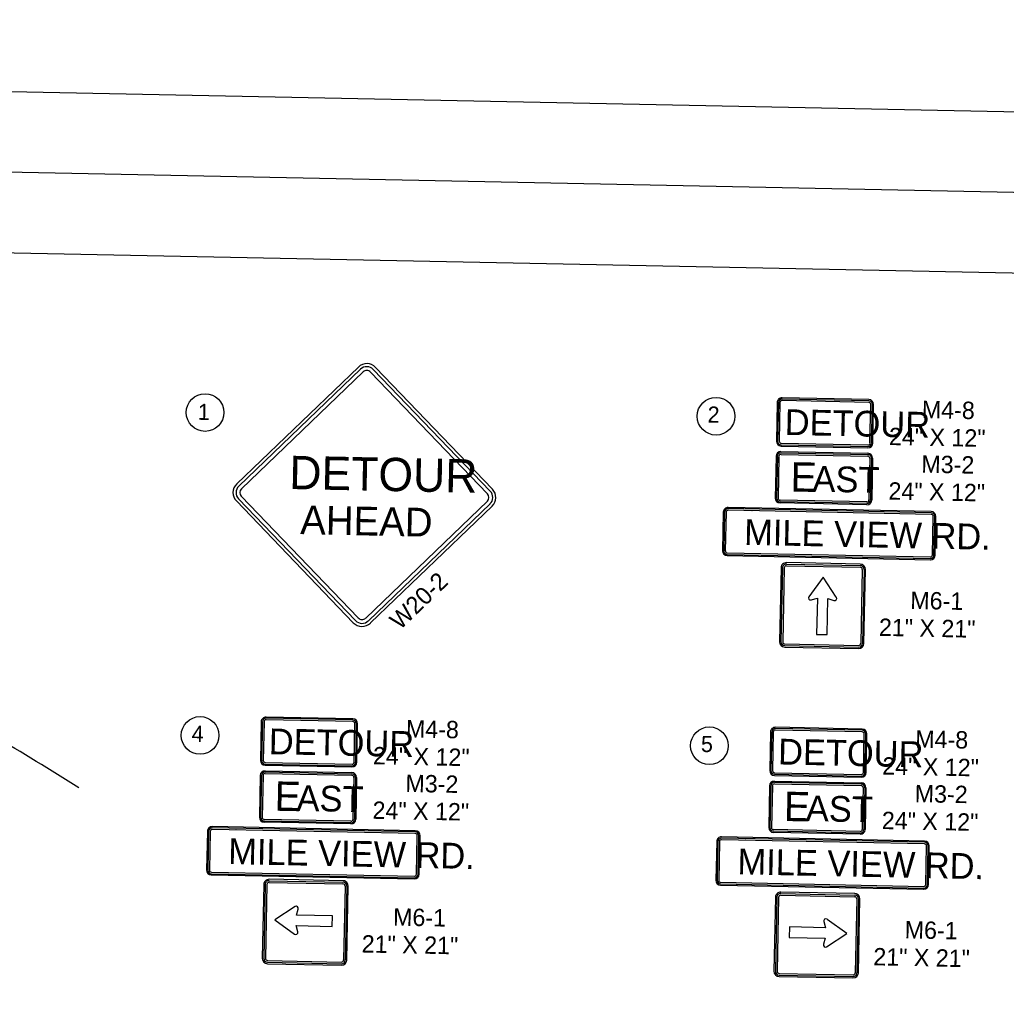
# Model space of a CAD drawing. Extents: x 299354 to 1325680, y 96128 to 228242.
# Drawn here: x 1319839 to 1322906, y 151826 to 154903 of the extents above; entities that cross this region are included whole.
import ezdxf

# ---------------------------------------------------------------- set-up
doc = ezdxf.new("R2010")
doc.units = 0
for name, color, linetype in [('CA-TEXT', 7, 'Continuous'), ('Level 4', 7, 'Continuous'), ('P_SGN_Cell', 7, 'Continuous'), ('PLT_Sheet_Border', 7, 'Continuous'), ('PLT_Sheet_Info', 7, 'Continuous')]:
    doc.layers.add(name, color=color, linetype=linetype)

msp = doc.modelspace()

# ---------------------------------------------------------------- linework, layer by layer
at = {"layer": 'CA-TEXT'}
for centre in [(1320414.9, 153681.8), (1322003.9, 153670.3), (1320399.5, 152677.4), (1321983.2, 152645.5)]:
    msp.add_circle(centre, 58.6, dxfattribs=at)
at = {"layer": 'Level 4'}
msp.add_spline([(1320022.4, 152514.1), (1319477, 152813.3), (1318978.2, 152936.2), (1318427, 152947.3), (1317374.5, 152955.9)], degree=3, dxfattribs=at)
at = {"layer": 'P_SGN_Cell'}
for p, q in [((1322205.9, 153560.4), (1322476.1, 153555)), ((1322206.1, 153556.6), (1322476, 153551.2)), ((1322190.8, 153545.7), (1322188.2, 153415.7)), ((1322194.6, 153545.6), (1322192, 153415.6)), ((1322199.6, 153545.5), (1322197, 153415.5)), ((1322206, 153551.6), (1322475.9, 153546.2)), ((1322482, 153539.8), (1322479.4, 153409.9)), ((1322487, 153539.7), (1322484.4, 153409.8)), ((1322490.8, 153539.7), (1322488.2, 153409.7)), ((1322472.9, 153395), (1322202.9, 153400.4)), ((1322472.9, 153398.7), (1322203, 153404.2)), ((1322473, 153403.7), (1322203.1, 153409.2)), ((1322206, 153198.7), (1322201.4, 152969.1)), ((1322210.4, 153198.6), (1322205.8, 152969)), ((1322215.9, 153198.5), (1322211.2, 152968.9)), ((1322222.6, 153205), (1322452.2, 153200.3)), ((1322222.7, 153210.4), (1322452.3, 153205.8)), ((1322452.4, 153210.2), (1322222.8, 153214.8)), ((1322458.6, 153193.7), (1322454, 152964)), ((1322464.1, 153193.5), (1322459.5, 152963.9)), ((1322463.8, 152963.8), (1322468.5, 153193.5)), ((1322336.7, 153169.8), (1322292.9, 153108.8)), ((1322378, 153107.1), (1322336.7, 153169.8)), ((1322300, 153098.7), (1322319, 153104)), ((1322319, 153104), (1322316.7, 152991.9)), ((1322349.5, 152991.3), (1322351.8, 153103.3)), ((1322351.8, 153103.3), (1322370.5, 153097.2)), ((1322316.7, 152991.9), (1322349.5, 152991.3)), ((1322217.5, 152952.4), (1322447.1, 152947.7)), ((1322217.6, 152956.7), (1322447.2, 152952.1)), ((1322217.7, 152962.2), (1322447.3, 152957.6)), ((1320586.5, 152552.8), (1320583.8, 152422.9)), ((1320590.2, 152552.8), (1320587.6, 152422.8)), ((1320595.2, 152552.7), (1320592.6, 152422.7)), ((1320601.6, 152567.5), (1320871.7, 152562.1)), ((1320601.6, 152558.8), (1320871.5, 152553.4)), ((1320601.7, 152563.8), (1320871.6, 152558.4)), ((1320877.6, 152547), (1320875, 152417)), ((1320882.6, 152546.9), (1320880, 152416.9)), ((1320886.4, 152546.8), (1320883.8, 152416.8)), ((1322170.2, 152520.9), (1322167.6, 152391)), ((1322174, 152520.9), (1322171.3, 152390.9)), ((1322179, 152520.8), (1322176.3, 152390.8)), ((1322185.3, 152535.6), (1322455.5, 152530.2)), ((1322185.3, 152526.9), (1322455.3, 152521.5)), ((1322185.4, 152531.9), (1322455.4, 152526.5)), ((1322461.4, 152515.1), (1322458.8, 152385.1)), ((1322466.4, 152515), (1322463.8, 152385)), ((1322470.1, 152514.9), (1322467.5, 152384.9)), ((1320868.7, 152410.9), (1320598.7, 152416.3)), ((1320868.5, 152402.1), (1320598.5, 152407.6)), ((1320868.6, 152405.9), (1320598.6, 152411.3)), ((1322452.4, 152379), (1322182.5, 152384.4)), ((1322452.2, 152370.2), (1322182.3, 152375.7)), ((1322452.3, 152374), (1322182.4, 152379.4)), ((1320597.6, 152213.9), (1320593, 151984.3)), ((1320602, 152213.8), (1320597.4, 151984.2)), ((1320607.5, 152213.7), (1320602.8, 151984.1)), ((1320614.2, 152220.2), (1320843.8, 152215.5)), ((1320614.3, 152225.6), (1320843.9, 152221)), ((1320844, 152225.4), (1320614.4, 152230)), ((1320850.2, 152208.8), (1320845.6, 151979.2)), ((1320855.7, 152208.7), (1320851.1, 151979.1)), ((1320855.4, 151979), (1320860.1, 152208.6)), ((1322188.7, 152174.1), (1322184, 151944.4)), ((1322193, 152174), (1322188.4, 151944.4)), ((1322198.5, 152173.9), (1322193.9, 151944.2)), ((1322205.2, 152180.3), (1322434.8, 152175.7)), ((1322205.3, 152185.8), (1322434.9, 152181.2)), ((1322435, 152185.5), (1322205.4, 152190.2)), ((1322441.3, 152169), (1322436.6, 151939.4)), ((1320695, 152145.1), (1320632.3, 152103.7)), ((1322446.7, 152168.9), (1322442.1, 151939.2)), ((1322446.5, 151939.2), (1322451.1, 152168.8)), ((1320698.8, 152118.8), (1320704.9, 152137.6)), ((1320810.9, 152116.5), (1320698.8, 152118.8)), ((1320810.2, 152083.7), (1320810.9, 152116.5)), ((1320632.3, 152103.7), (1320693.3, 152059.9)), ((1320703.5, 152067), (1320698.1, 152086)), ((1320698.1, 152086), (1320810.2, 152083.7)), ((1322232.4, 152081.7), (1322231.7, 152048.9)), ((1322344.4, 152079.5), (1322232.4, 152081.7)), ((1322339.1, 152098.4), (1322344.4, 152079.5)), ((1322410.3, 152061.7), (1322349.3, 152105.5)), ((1322231.7, 152048.9), (1322343.8, 152046.6)), ((1322343.8, 152046.6), (1322337.7, 152027.9)), ((1322347.5, 152020.4), (1322410.3, 152061.7)), ((1320609.1, 151967.6), (1320838.7, 151962.9)), ((1320609.2, 151971.9), (1320838.8, 151967.3)), ((1320609.3, 151977.4), (1320838.9, 151972.8)), ((1322200.1, 151927.7), (1322429.8, 151923.1)), ((1322200.2, 151932.1), (1322429.8, 151927.5)), ((1322200.3, 151937.5), (1322430, 151932.9))]:
    msp.add_line(p, q, dxfattribs=at)
for points in [[(1320891.9, 153823.3), (1320513.3, 153459.6)], [(1320898.5, 153816.4), (1320519.9, 153452.7)], [(1320906.8, 153807.8), (1320528.2, 153444.2)], [(1321293.2, 153428.8), (1320929.5, 153807.4)], [(1321301.8, 153437), (1320938.1, 153815.6)], [(1321308.7, 153443.6), (1320945, 153822.2)], [(1322194, 153712.8), (1322191.6, 153592.9)], [(1322197.7, 153712.8), (1322195.3, 153592.8)], [(1322202.7, 153712.7), (1322200.3, 153592.7)], [(1322479, 153713.3), (1322209.1, 153718.8)], [(1322479.1, 153718.3), (1322209.2, 153723.8)], [(1322479.2, 153722.1), (1322209.3, 153727.5)], [(1322482.7, 153587), (1322485.2, 153707)], [(1322487.7, 153586.9), (1322490.2, 153706.9)], [(1322491.5, 153586.8), (1322493.9, 153706.8)], [(1322206.4, 153586.3), (1322476.4, 153580.9)], [(1322206.2, 153577.6), (1322476.2, 153572.1)], [(1322206.3, 153581.3), (1322476.3, 153575.9)], [(1320512.3, 153406.6), (1320875.9, 153028)], [(1320519.1, 153413.2), (1320882.8, 153034.6)], [(1320527.7, 153421.4), (1320891.4, 153042.8)], [(1320914.4, 153042.6), (1321292.9, 153406.2)], [(1320922.7, 153034.1), (1321301.2, 153397.6)], [(1320929.3, 153027.2), (1321307.8, 153390.7)], [(1322026.5, 153371.8), (1322024.1, 153251.9)], [(1322030.3, 153371.8), (1322027.8, 153251.8)], [(1322035.3, 153371.7), (1322032.8, 153251.7)], [(1322673, 153365.1), (1322041.6, 153377.8)], [(1322673.1, 153370.1), (1322041.7, 153382.8)], [(1322673.2, 153373.8), (1322041.8, 153386.8)], [(1322676.7, 153238.7), (1322679.1, 153358.7)], [(1322681.7, 153238.6), (1322684.1, 153358.6)], [(1322685.5, 153238.6), (1322687.9, 153358.5)], [(1322038.8, 153236.6), (1322670.9, 153223.8)], [(1322038.9, 153240.3), (1322670.2, 153227.6)], [(1322039, 153245.3), (1322670.3, 153232.6)], [(1320874.6, 152720.5), (1320604.7, 152725.9)], [(1320874.7, 152725.5), (1320604.8, 152730.9)], [(1320874.8, 152729.2), (1320604.9, 152734.7)], [(1320589.6, 152720), (1320587.2, 152600)], [(1320593.3, 152719.9), (1320590.9, 152599.9)], [(1320598.3, 152719.8), (1320595.9, 152599.8)], [(1320878.4, 152594.1), (1320880.8, 152714.1)], [(1320883.4, 152594), (1320885.8, 152714)], [(1320887.1, 152594), (1320889.5, 152713.9)], [(1322458.4, 152688.6), (1322188.5, 152694)], [(1322458.6, 152697.3), (1322188.6, 152702.8)], [(1322458.5, 152693.6), (1322188.6, 152699)], [(1322173.3, 152688.1), (1322170.9, 152568.1)], [(1322177.1, 152688), (1322174.7, 152568)], [(1322182.1, 152687.9), (1322179.7, 152567.9)], [(1322462.1, 152562.2), (1322464.5, 152682.2)], [(1322467.1, 152562.1), (1322469.5, 152682.1)], [(1322470.9, 152562.1), (1322473.3, 152682)], [(1320601.9, 152588.5), (1320871.9, 152583)], [(1320601.9, 152584.7), (1320871.8, 152579.3)], [(1320602, 152593.5), (1320872, 152588)], [(1322185.6, 152552.8), (1322455.6, 152547.4)], [(1322185.7, 152556.6), (1322455.6, 152551.1)], [(1322185.8, 152561.6), (1322455.7, 152556.1)], [(1321068.6, 152372.2), (1320437.2, 152384.9)], [(1321068.7, 152377.2), (1320437.3, 152389.9)], [(1321068.8, 152381), (1320437.4, 152393.9)], [(1320422.1, 152379), (1320419.7, 152259)], [(1320425.9, 152378.9), (1320423.5, 152258.9)], [(1320430.9, 152378.8), (1320428.5, 152258.8)], [(1321072.3, 152245.9), (1321074.7, 152365.9)], [(1321077.3, 152245.8), (1321079.7, 152365.8)], [(1321081.1, 152245.7), (1321083.5, 152365.7)], [(1322652.5, 152345.3), (1322021.1, 152358)], [(1322652.5, 152349.1), (1322021.2, 152362)], [(1322005.9, 152347.1), (1322003.5, 152227.1)], [(1322009.6, 152347), (1322007.2, 152227.1)], [(1322014.6, 152346.9), (1322012.2, 152227)], [(1322652.4, 152340.3), (1322021, 152353)], [(1322656.1, 152214), (1322658.5, 152334)], [(1322661.1, 152213.9), (1322663.5, 152333.9)], [(1322664.8, 152213.8), (1322667.2, 152333.8)], [(1320434.4, 152243.7), (1321066.5, 152231)], [(1320434.5, 152247.5), (1321065.8, 152234.8)], [(1320434.6, 152252.5), (1321065.9, 152239.8)], [(1322018.2, 152215.6), (1322649.6, 152202.9)], [(1322018.2, 152211.8), (1322650.3, 152199.1)], [(1322018.3, 152220.6), (1322649.7, 152207.9)]]:
    msp.add_lwpolyline(points, dxfattribs=at)
for centre, radius, start, end in [((1320917.9, 153796.3), 37.5, 43.8449, 133.8468), ((1320917.9, 153796.3), 28, 43.8449, 133.8468), ((1320917.9, 153796.3), 16.1, 43.8449, 133.8468), ((1322209, 153712.5), 15, 88.8468, 178.8468), ((1322209, 153712.5), 11.2, 88.8468, 178.8468), ((1322209, 153712.5), 6.25, 88.8468, 178.8468), ((1322209, 153712.5), 6.25, 88.8468, 96.1883), ((1322478.9, 153707.1), 6.25, 358.8468, 88.8468), ((1322478.9, 153707.1), 11.2, 358.8468, 88.8468), ((1322478.9, 153707.1), 15, 358.8468, 88.8468), ((1322206.6, 153592.6), 15, 178.8468, 268.8468), ((1322206.6, 153592.6), 11.2, 178.8468, 268.8468), ((1322206.6, 153592.6), 6.25, 178.8468, 268.8468), ((1322476.5, 153587.1), 15, 268.8468, 358.8468), ((1322476.5, 153587.1), 11.2, 268.8468, 358.8468), ((1322476.5, 153587.1), 6.25, 268.8468, 358.8468), ((1322205.8, 153545.4), 15, 89.6119, 178.8462), ((1322205.8, 153545.4), 11.2, 88.8462, 178.8462), ((1322475.8, 153540), 15, 358.8462, 88.8462), ((1322205.8, 153545.4), 6.25, 88.8462, 178.8462), ((1322475.8, 153540), 6.25, 358.8462, 88.8462), ((1322475.8, 153540), 11.2, 358.8462, 88.8462), ((1320539.3, 153432.6), 37.5, 133.8468, 223.8468), ((1320539.3, 153432.6), 28, 133.8468, 223.8468), ((1320539.3, 153432.6), 16.1, 133.8468, 223.8468), ((1321281.6, 153417.6), 28, 313.8468, 43.8468), ((1321281.6, 153417.6), 37.5, 313.8468, 43.8468), ((1321281.6, 153417.6), 16.1, 313.8468, 43.8468), ((1322203.2, 153415.4), 15, 178.8462, 268.8462), ((1322203.2, 153415.4), 11.2, 178.8462, 268.8462), ((1322203.2, 153415.4), 6.25, 178.8462, 268.8462), ((1322473.2, 153410), 11.2, 268.8462, 358.8462), ((1322473.2, 153410), 15, 268.8462, 358.8462), ((1322473.2, 153410), 6.25, 268.8462, 358.8462), ((1322041.5, 153371.7), 15, 88.8468, 178.8468), ((1322041.5, 153371.5), 11.2, 88.8468, 178.8468), ((1322041.5, 153371.5), 6.25, 88.8468, 178.8468), ((1322115.9, 153370), 6.25, 88.8468, 96.1883), ((1322672.9, 153358.8), 11.2, 358.8468, 88.8468), ((1322672.9, 153358.8), 15, 358.8468, 88.8468), ((1322672.9, 153358.8), 6.25, 358.8468, 88.8468), ((1322039.1, 153251.6), 15, 178.8468, 268.8468), ((1322039.1, 153251.6), 11.2, 178.8468, 268.8468), ((1322039.1, 153251.6), 6.25, 178.8468, 268.8468), ((1322670.5, 153238.9), 15, 268.8468, 358.8468), ((1322670.5, 153238.9), 11.2, 268.8468, 358.8468), ((1322670.5, 153238.9), 6.25, 268.8468, 358.8468), ((1322222.4, 153198.4), 16.4, 88.8468, 178.8468), ((1322222.4, 153198.4), 12, 88.8468, 178.8468), ((1322222.4, 153198.4), 6.56, 88.8468, 178.8468), ((1322452.1, 153193.8), 6.56, 358.8468, 88.8468), ((1322452.1, 153193.8), 12, 358.8468, 88.8468), ((1322452.1, 153193.8), 16.4, 59.4503, 88.8468), ((1322452.1, 153193.8), 16.4, 358.8468, 88.8468), ((1322298.2, 153105), 6.56, 144.3172, 285.6494), ((1322372.6, 153103.5), 6.56, 252.0442, 33.3765), ((1320903, 153053.9), 28, 223.854, 314.4977), ((1320903, 153053.9), 16.1, 223.854, 314.4977), ((1320903, 153053.9), 37.5, 223.854, 314.4977), ((1322217.8, 152968.8), 16.4, 178.8468, 268.8468), ((1322217.8, 152968.8), 12, 178.8468, 268.8468), ((1322217.8, 152968.8), 6.56, 178.8468, 268.8468), ((1322447.4, 152964.1), 16.4, 268.8468, 358.8468), ((1322447.4, 152964.1), 12, 268.8468, 358.8468), ((1322447.4, 152964.1), 6.56, 268.8468, 358.8468), ((1320604.6, 152719.7), 15, 88.8468, 178.8468), ((1320604.6, 152719.7), 11.2, 88.8468, 178.8468), ((1320604.6, 152719.7), 6.25, 88.8468, 178.8468), ((1320604.6, 152719.7), 6.25, 88.8468, 96.1883), ((1320874.5, 152714.2), 11.2, 358.8468, 88.8468), ((1320874.5, 152714.2), 15, 358.8468, 88.8468), ((1320874.5, 152714.2), 6.25, 358.8468, 88.8468), ((1322188.3, 152687.8), 15, 88.8468, 178.8468), ((1322188.3, 152687.8), 11.2, 88.8468, 178.8468), ((1322188.3, 152687.8), 6.25, 88.8468, 178.8468), ((1322188.3, 152687.8), 6.25, 88.8468, 96.1883), ((1322458.3, 152682.3), 11.2, 358.8468, 88.8468), ((1322458.3, 152682.3), 15, 358.8468, 88.8468), ((1322458.3, 152682.3), 6.25, 358.8468, 88.8468), ((1320602.2, 152599.7), 15, 178.8468, 268.8468), ((1320602.2, 152599.7), 11.2, 178.8468, 268.8468), ((1320602.2, 152599.7), 6.25, 178.8468, 268.8468), ((1320872.1, 152594.3), 15, 268.8468, 358.8468), ((1320872.1, 152594.3), 11.2, 268.8468, 358.8468), ((1320872.1, 152594.3), 6.25, 268.8468, 358.8468), ((1320601.5, 152552.5), 15, 89.6119, 178.8462), ((1320601.5, 152552.5), 11.2, 88.8462, 178.8462), ((1320601.5, 152552.5), 6.25, 88.8462, 178.8462), ((1320871.4, 152547.1), 6.25, 358.8462, 88.8462), ((1320871.4, 152547.1), 11.2, 358.8462, 88.8462), ((1320871.4, 152547.1), 15, 358.8462, 88.8462), ((1322185.9, 152567.8), 15, 178.8468, 268.8468), ((1322185.9, 152567.8), 11.2, 178.8468, 268.8468), ((1322185.9, 152567.8), 6.25, 178.8468, 268.8468), ((1322455.9, 152562.4), 15, 268.8468, 358.8468), ((1322455.9, 152562.4), 11.2, 268.8468, 358.8468), ((1322455.9, 152562.4), 6.25, 268.8468, 358.8468), ((1322185.2, 152520.6), 15, 89.6119, 178.8462), ((1322185.2, 152520.6), 11.2, 88.8462, 178.8462), ((1322185.2, 152520.6), 6.25, 88.8462, 178.8462), ((1322455.1, 152515.2), 6.25, 358.8462, 88.8462), ((1322455.1, 152515.2), 11.2, 358.8462, 88.8462), ((1322455.1, 152515.2), 15, 358.8462, 88.8462), ((1320598.8, 152422.6), 15, 178.8462, 268.8462), ((1320598.8, 152422.6), 11.2, 178.8462, 268.8462), ((1320598.8, 152422.6), 6.25, 178.8462, 268.8462), ((1320868.8, 152417.1), 15, 268.8462, 358.8462), ((1320868.8, 152417.1), 11.2, 268.8462, 358.8462), ((1320868.8, 152417.1), 6.25, 268.8462, 358.8462), ((1320437.1, 152378.9), 15, 88.8468, 178.8468), ((1320437.1, 152378.7), 11.2, 88.8468, 178.8468), ((1320437.1, 152378.7), 6.25, 88.8468, 178.8468), ((1322182.6, 152390.7), 15, 178.8462, 268.8462), ((1322182.6, 152390.7), 11.2, 178.8462, 268.8462), ((1322182.6, 152390.7), 6.25, 178.8462, 268.8462), ((1322452.5, 152385.2), 15, 268.8462, 358.8462), ((1322452.5, 152385.2), 11.2, 268.8462, 358.8462), ((1322452.5, 152385.2), 6.25, 268.8462, 358.8462), ((1320511.6, 152377.2), 6.25, 88.8468, 96.1883), ((1321068.5, 152366), 6.25, 358.8468, 88.8468), ((1321068.5, 152366), 11.2, 358.8468, 88.8468), ((1321068.5, 152366), 15, 358.8468, 88.8468), ((1322020.9, 152347), 15, 88.8468, 178.8468), ((1322020.9, 152346.8), 11.2, 88.8468, 178.8468), ((1322020.9, 152346.8), 6.25, 88.8468, 178.8468), ((1322095.3, 152345.3), 6.25, 88.8468, 96.1883), ((1322652.2, 152334.1), 6.25, 358.8468, 88.8468), ((1322652.2, 152334.1), 15, 358.8468, 88.8468), ((1322652.2, 152334.1), 11.2, 358.8468, 88.8468), ((1320434.7, 152258.7), 15, 178.8468, 268.8468), ((1320434.7, 152258.7), 11.2, 178.8468, 268.8468), ((1320434.7, 152258.7), 6.25, 178.8468, 268.8468), ((1321066.1, 152246), 11.2, 268.8468, 358.8468), ((1321066.1, 152246), 15, 268.8468, 358.8468), ((1321066.1, 152246), 6.25, 268.8468, 358.8468), ((1320614, 152213.6), 16.4, 88.8468, 178.8468), ((1320614, 152213.6), 12, 88.8468, 178.8468), ((1320614, 152213.6), 6.56, 88.8468, 178.8468), ((1320843.7, 152209), 6.56, 358.8468, 88.8468), ((1320843.7, 152209), 12, 358.8468, 88.8468), ((1320843.7, 152209), 16.4, 59.4503, 88.8468), ((1320843.7, 152209), 16.4, 358.8468, 88.8468), ((1322018.5, 152226.8), 15, 178.8468, 268.8468), ((1322018.5, 152226.8), 11.2, 178.8468, 268.8468), ((1322018.5, 152226.8), 6.25, 178.8468, 268.8468), ((1322649.8, 152214.1), 15, 268.8468, 358.8468), ((1322649.8, 152214.1), 11.2, 268.8468, 358.8468), ((1322649.8, 152214.1), 6.25, 268.8468, 358.8468), ((1322205.1, 152173.8), 16.4, 88.8468, 178.8468), ((1322205.1, 152173.8), 12, 88.8468, 178.8468), ((1322205.1, 152173.8), 6.56, 88.8468, 178.8468), ((1322434.7, 152169.1), 6.56, 358.8468, 88.8468), ((1322434.7, 152169.1), 12, 358.8468, 88.8468), ((1322434.7, 152169.1), 16.4, 59.4503, 88.8468), ((1322434.7, 152169.1), 16.4, 358.8468, 88.8468), ((1320698.6, 152139.6), 6.56, 342.0442, 123.3765), ((1322345.4, 152100.2), 6.56, 54.3172, 195.6494), ((1320697.1, 152065.2), 6.56, 234.3172, 15.6494), ((1322343.9, 152025.9), 6.56, 162.0442, 303.3765), ((1320609.4, 151984), 16.4, 178.8468, 268.8468), ((1320609.4, 151984), 12, 178.8468, 268.8468), ((1320609.4, 151984), 6.56, 178.8468, 268.8468), ((1320839, 151979.3), 16.4, 268.8468, 358.8468), ((1320839, 151979.3), 12, 268.8468, 358.8468), ((1320839, 151979.3), 6.56, 268.8468, 358.8468), ((1322200.4, 151944.1), 16.4, 178.8468, 268.8468), ((1322200.4, 151944.1), 12, 178.8468, 268.8468), ((1322200.4, 151944.1), 6.56, 178.8468, 268.8468), ((1322430.1, 151939.5), 12, 268.8468, 358.8468), ((1322430.1, 151939.5), 16.4, 268.8468, 358.8468), ((1322430.1, 151939.5), 6.56, 268.8468, 358.8468)]:
    msp.add_arc(centre, radius, start, end, dxfattribs=at)
at = {"layer": 'PLT_Sheet_Border'}
for points in [[(1308461.6, 143905.4), (1325458.1, 143563.1), (1325679.6, 154560.9), (1308683.1, 154903.2)], [(1308586.6, 144153), (1325133.2, 143819.7), (1325344.6, 154317.6), (1308798, 154650.9)]]:
    msp.add_lwpolyline(points, close=True, dxfattribs=at)
at = {"layer": 'PLT_Sheet_Info'}
msp.add_line((1309305.4, 154390.6), (1325052.2, 154073.4), dxfattribs=at)

# ---------------------------------------------------------------- texts
at = {"layer": 'CA-TEXT'}
for s, p in [('1', (1320392.4, 153659.2)), ('2', (1321977.2, 153650.8)), ('4', (1320372.8, 152658)), ('5', (1321956.6, 152626.1))]:
    msp.add_text(s, height=50, rotation=358.8468, dxfattribs=at).set_placement(p)
at = {"layer": 'P_SGN_Cell'}
for s, height, rotation, p in [('M4-8', 54, 358.8468, (1322643.6, 153664.4)), ('DETOUR', 80, 358.8468, (1322217, 153612.2)), ('24" X 12"', 54, 358.8468, (1322541.3, 153580.7)), ('DETOUR', 103.57, 358.8468, (1320676.2, 153443.9)), ('E', 91.4, 358.8462, (1322235, 153436.2)), ('M3-2', 54, 358.8462, (1322642, 153494.8)), ('AST', 80, 358.8462, (1322303.3, 153435.9)), ('24" X 12"', 54, 358.8462, (1322539.7, 153411.1)), ('AHEAD', 89.29, 358.8468, (1320710.2, 153303.6)), ('MILE VIEW RD.', 80, 358.8468, (1322090.8, 153270.3)), ('W20-2', 54, 43.8468, (1321021.1, 153003.4)), ('M6-1', 54, 358.8468, (1322607.6, 153071)), ('21" X 21"', 54, 358.8468, (1322510, 152987.3)), ('M4-8', 54, 358.8468, (1321039.2, 152671.6)), ('DETOUR', 80, 358.8468, (1320612.6, 152619.3)), ('M4-8', 54, 358.8468, (1322623, 152639.7)), ('DETOUR', 80, 358.8468, (1322196.4, 152587.4)), ('24" X 12"', 54, 358.8468, (1320936.9, 152587.9)), ('24" X 12"', 54, 358.8468, (1322520.6, 152556)), ('M3-2', 54, 358.8462, (1321037.6, 152501.9)), ('E', 91.4, 358.8462, (1320630.6, 152443.3)), ('AST', 80, 358.8462, (1320698.9, 152443.1)), ('M3-2', 54, 358.8462, (1322621.4, 152470)), ('E', 91.4, 358.8462, (1322214.3, 152411.4)), ('AST', 80, 358.8462, (1322282.7, 152411.2)), ('24" X 12"', 54, 358.8462, (1320935.3, 152418.3)), ('24" X 12"', 54, 358.8462, (1322519, 152386.4)), ('MILE VIEW RD.', 80, 358.8468, (1320486.4, 152277.5)), ('MILE VIEW RD.', 80, 358.8468, (1322070.1, 152245.6)), ('M6-1', 54, 358.8468, (1320999.2, 152086.2)), ('M6-1', 54, 358.8468, (1322590.2, 152046.4)), ('21" X 21"', 54, 358.8468, (1320901.6, 152002.5)), ('21" X 21"', 54, 358.8468, (1322492.6, 151962.6))]:
    msp.add_text(s, height=height, rotation=rotation, dxfattribs=at).set_placement(p)

doc.saveas('drawing.dxf')
